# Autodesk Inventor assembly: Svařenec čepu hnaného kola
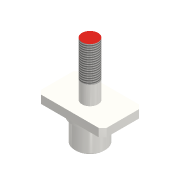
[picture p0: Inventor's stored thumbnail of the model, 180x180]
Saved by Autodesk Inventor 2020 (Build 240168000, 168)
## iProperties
Created: 2025-03
Part Number: Svařenec čepu hnaného kola
Document SubType Name: Assembly
Designer: doma
Mass: 418.811 g
Surface Area: 152.681 cm^2
Volume: 53.3517 cm^3
Density: 7.85 g/cm^3
Author: doma
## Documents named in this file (3)
- C:\Users\doma\Desktop\Pásovka záloha\Workgroups\NotInProject\Svařenec čepu hnaného kola.iam
- C:\Users\doma\Desktop\Pásovka záloha\Workgroups\NotInProject\Čep hnaného kola.ipt
- C:\Users\doma\Desktop\Pásovka záloha\Workgroups\NotInProject\Vedení hnaného kola 2.ipt
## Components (2 placed, 2 different names)
1. Čep hnaného kola:1 — Proti sobě:1, Proti sobě:2
2. Vedení hnaného kola 2:1 — Proti sobě:1, Proti sobě:2
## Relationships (2: Mate 2)
- Proti sobě:1 [Mate]: Čep hnaného kola:1 ↔ Vedení hnaného kola 2:1
- Proti sobě:2 [Mate]: Čep hnaného kola:1 ↔ Vedení hnaného kola 2:1
